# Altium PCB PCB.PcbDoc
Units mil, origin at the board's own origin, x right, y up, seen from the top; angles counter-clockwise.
Board outline 6000 x 4000 mil, 2 copper layers (Top Layer, Bottom Layer); 2 components, 0 nets, 15 pads, 0 vias.
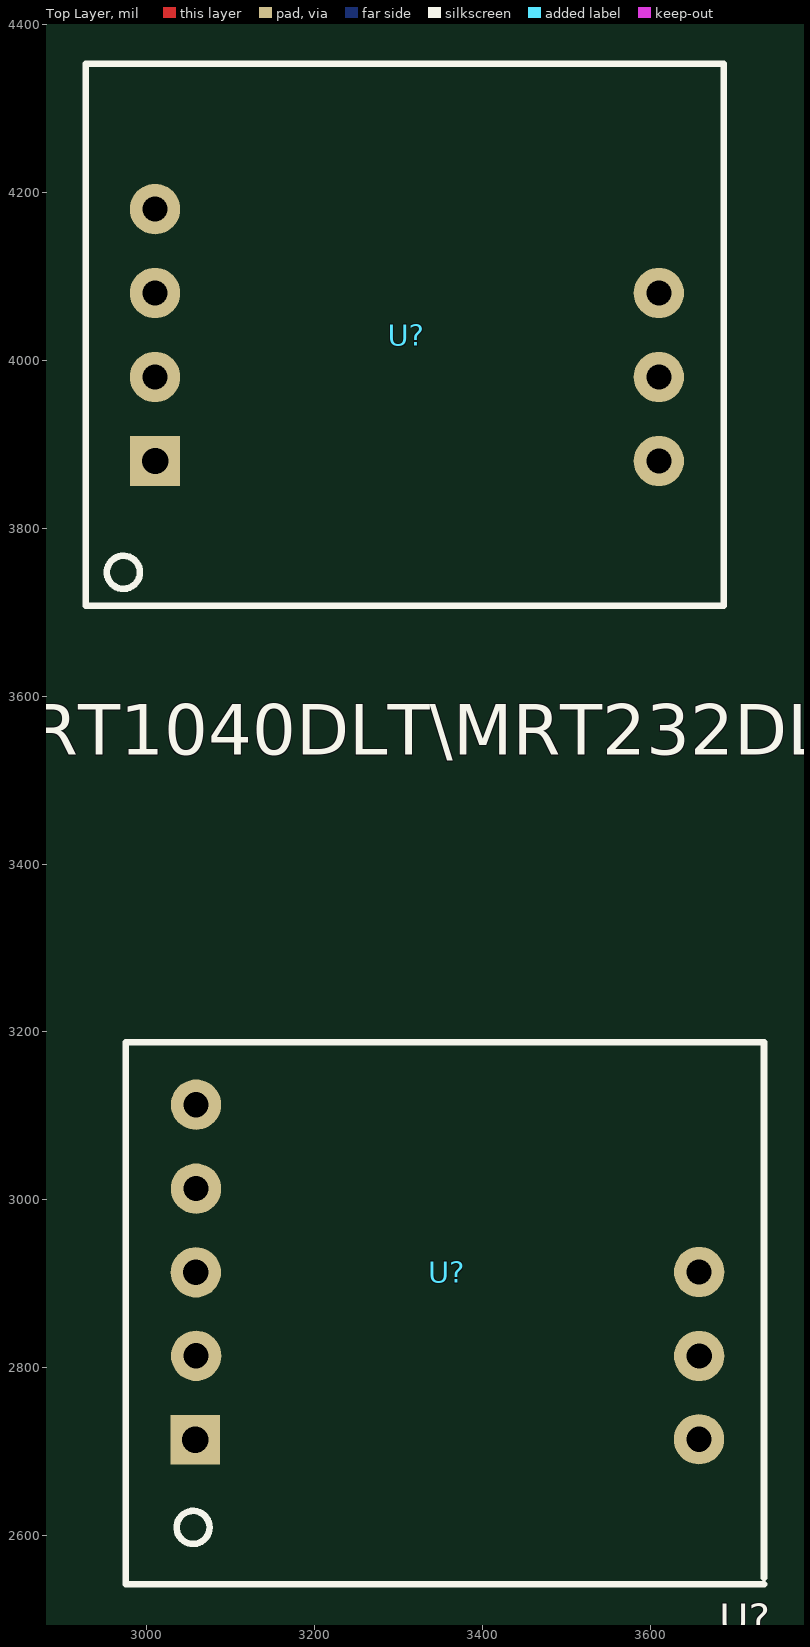
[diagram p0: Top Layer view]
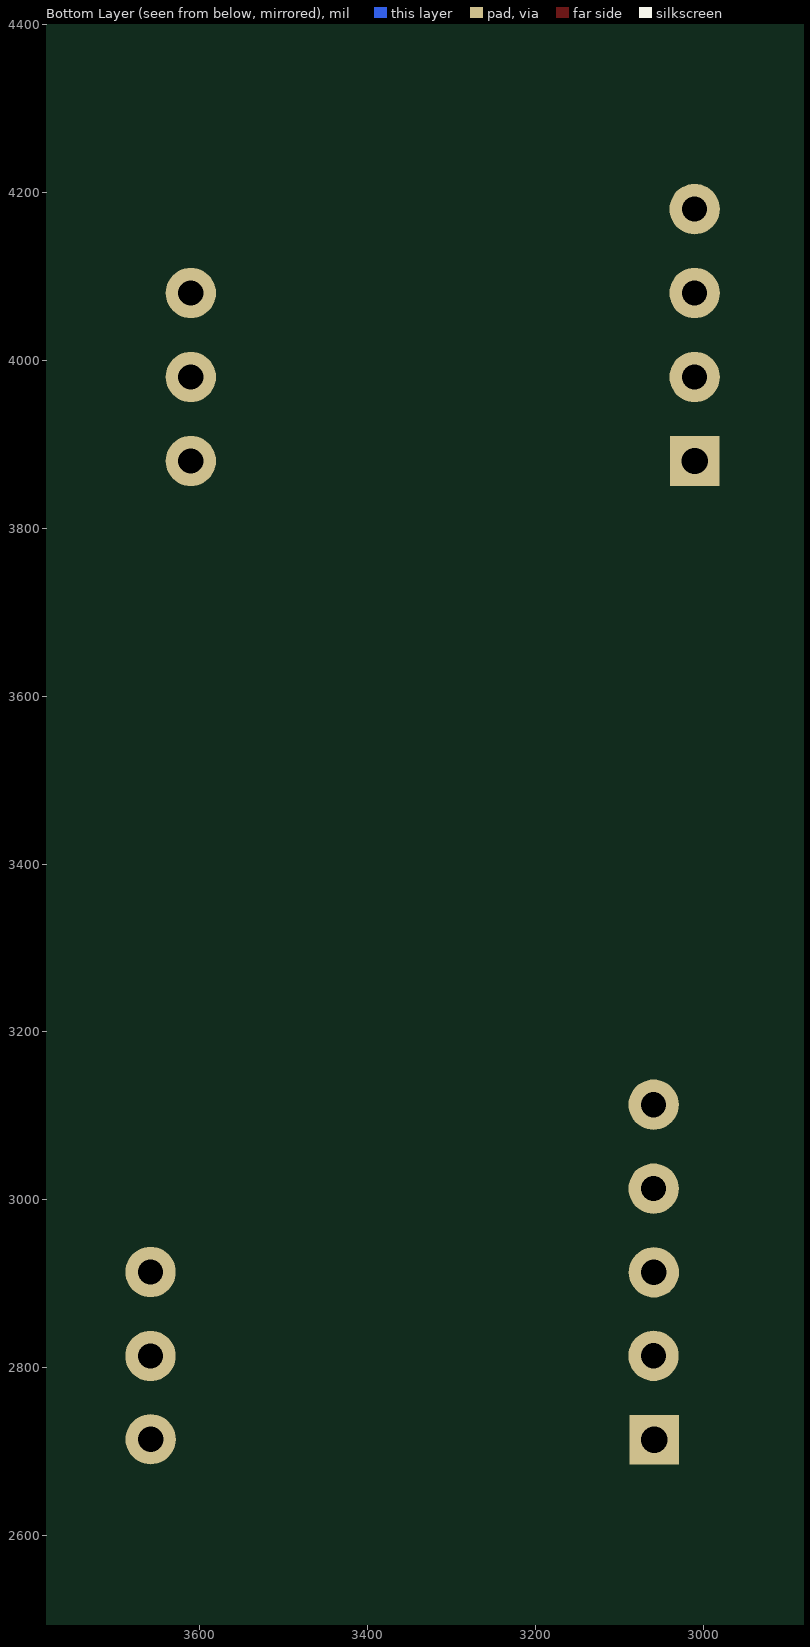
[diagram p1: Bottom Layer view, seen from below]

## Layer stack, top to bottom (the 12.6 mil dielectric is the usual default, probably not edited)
Top Layer: signal copper 1.4
Dielectric: dielectric 12.6, FR-4, Dk 4.8
Bottom Layer: signal copper 1.4

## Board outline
1000,1000 7000,1000 7000,5000 1000,5000

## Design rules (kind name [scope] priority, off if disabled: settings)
Clearance [All] p1: gap=10
PolygonConnect [All] p1: connectstyle=Relief reliefconductorwidth=10 reliefentries=4 polygonreliefangle="90 Angle" airgapwidth=10
RoutingVias [All] p1: holewidth=28 width=50 viastyle="Through Hole" minholewidth=28 minwidth=50 maxholewidth=28 maxwidth=50
SilkscreenOverComponentPads [All] p1: minsilkscreentomaskgap=10
SolderMaskExpansion [All] p1: expansion=4
Width [All] p1: maxlimit=10 minlimit=10 preferedwidth=10
27 further rules are at their usual default settings.

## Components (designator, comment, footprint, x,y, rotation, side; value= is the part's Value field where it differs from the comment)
U? "MRT485DLT\MRT485DHT\MRT485DUT" RS485_1050 3358,2914 r0 top
U? "MRT1040DLT\MRT232DLT" RS485 3010,3880 r0 top

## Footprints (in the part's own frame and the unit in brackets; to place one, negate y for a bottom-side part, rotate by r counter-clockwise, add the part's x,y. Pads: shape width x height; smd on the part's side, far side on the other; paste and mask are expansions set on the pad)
RS485 [mil]
  rect 59.05x59.05 hole 31.5: 1(0,0)
  round 60 hole 30: 2(0,100) 3(0,200) 4(0,300) 6(600,200) 7(600,100) 8(600,0)
  silkscreen extent -83,-172 677,473
RS485_1050 [mil]
  rect 59.05x59.05 hole 31.5: 1(-300.01,-199.42)
  round 60 hole 30: 2(-299.09,-99.64) 3(-299.42,-0.19) 4(-299.16,99.48) 5(-299.15,199.42) 8(299.93,0.19) 9(300.01,-99.85) 10(299.77,-199.02)
  silkscreen extent -383,-372 377,274

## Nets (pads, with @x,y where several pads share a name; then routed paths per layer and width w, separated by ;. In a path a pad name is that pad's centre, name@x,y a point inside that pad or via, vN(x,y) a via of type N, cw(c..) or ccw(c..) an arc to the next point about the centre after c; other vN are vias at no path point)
pads on no net: U?.1 U?.2 U?.3 U?.4 U?.5 U?.6 U?.7 U?.8 U?.9 U?.10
